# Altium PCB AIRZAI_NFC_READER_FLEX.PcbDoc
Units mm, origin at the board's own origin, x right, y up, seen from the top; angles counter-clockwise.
Board outline 158.45 x 20.7 mm, 2 copper layers (Top Layer, Bottom Layer); 39 components, 43 nets, 189 pads, 9 vias.
Unrouted connection lines stored in the file: 129.
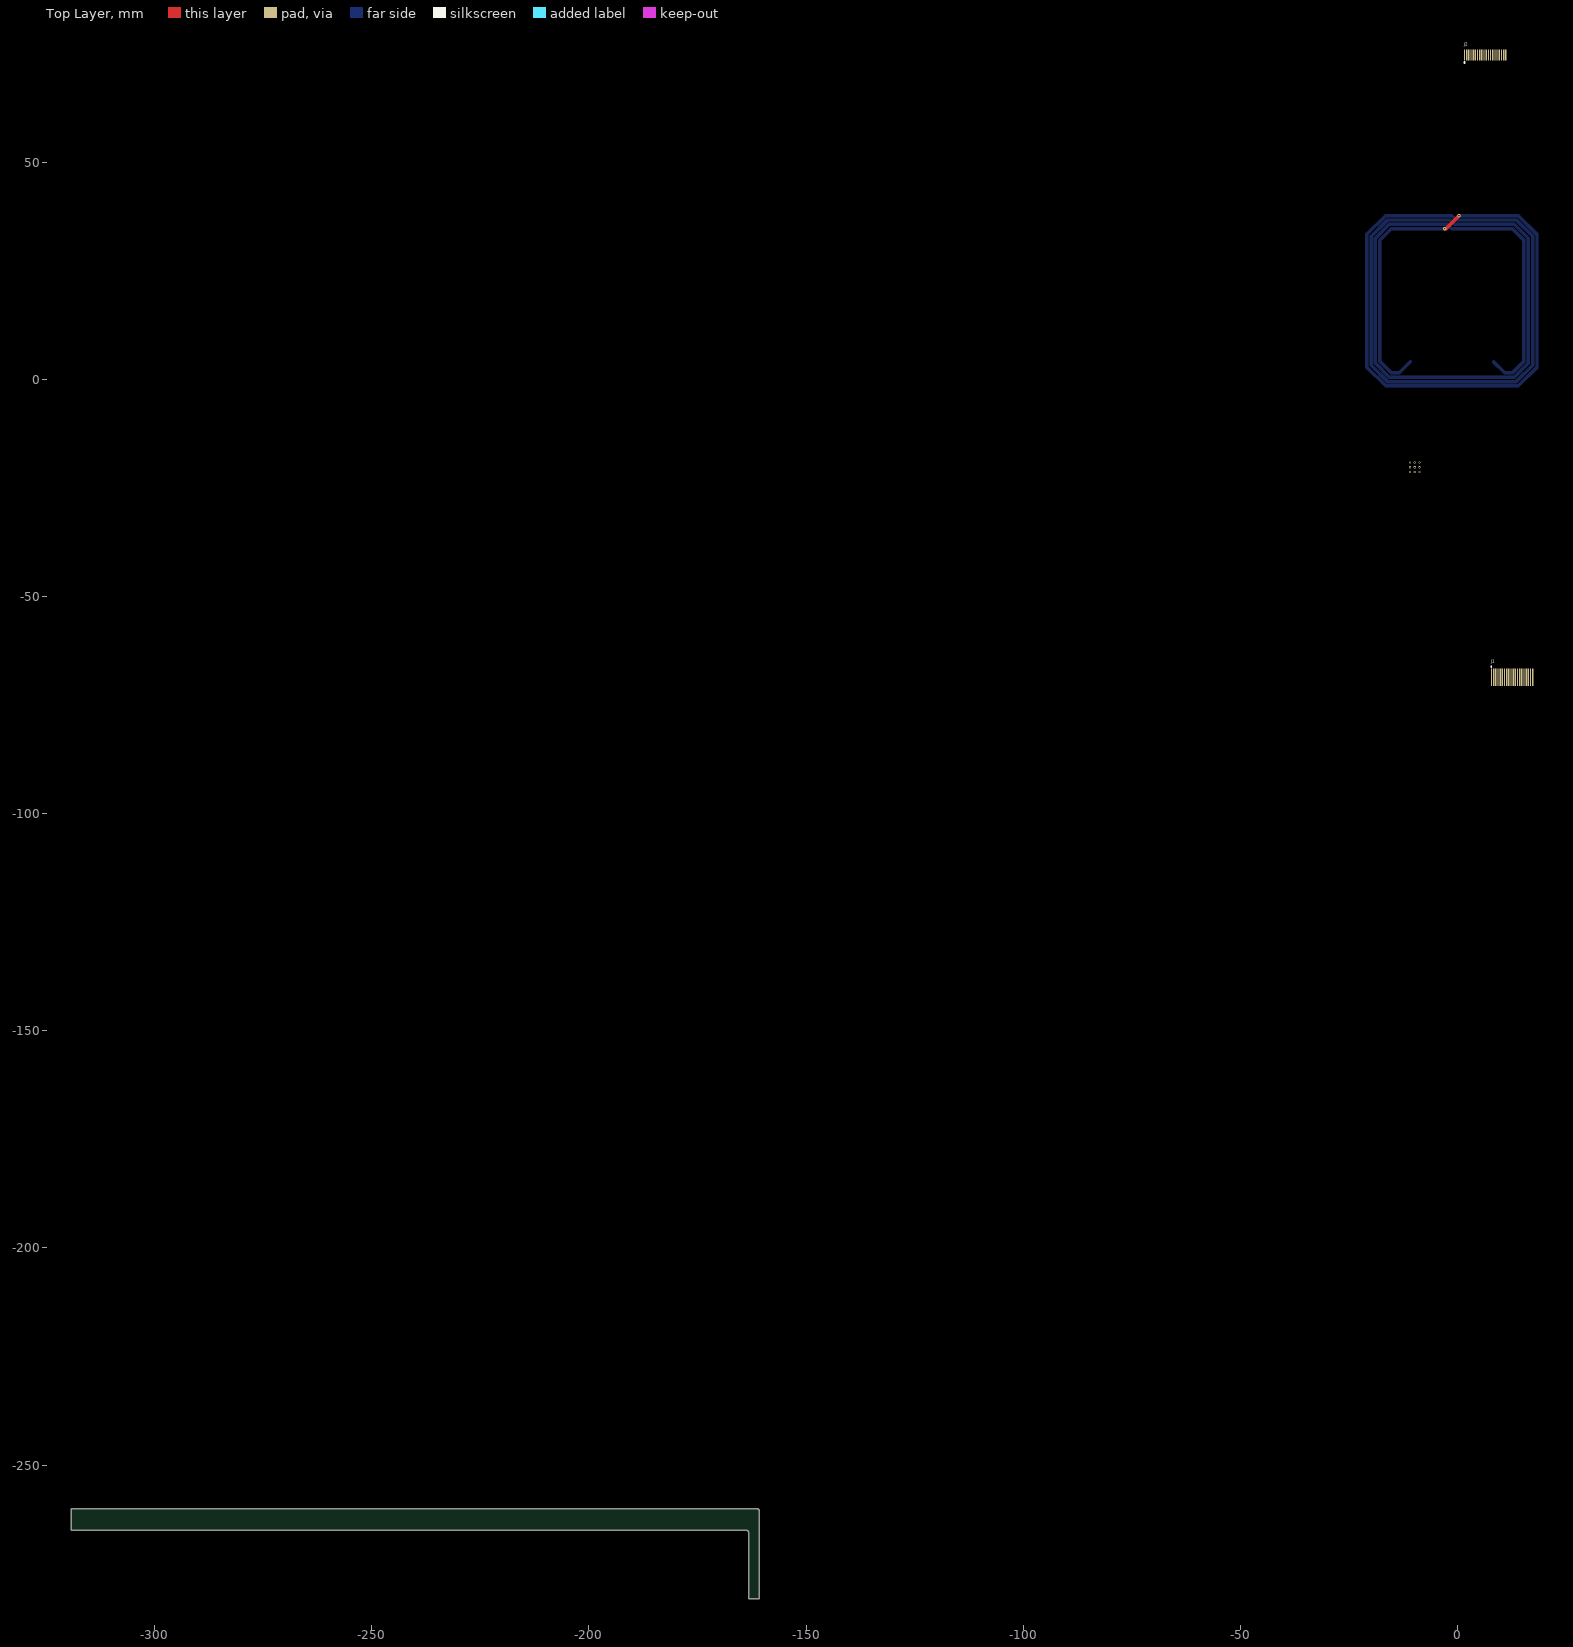
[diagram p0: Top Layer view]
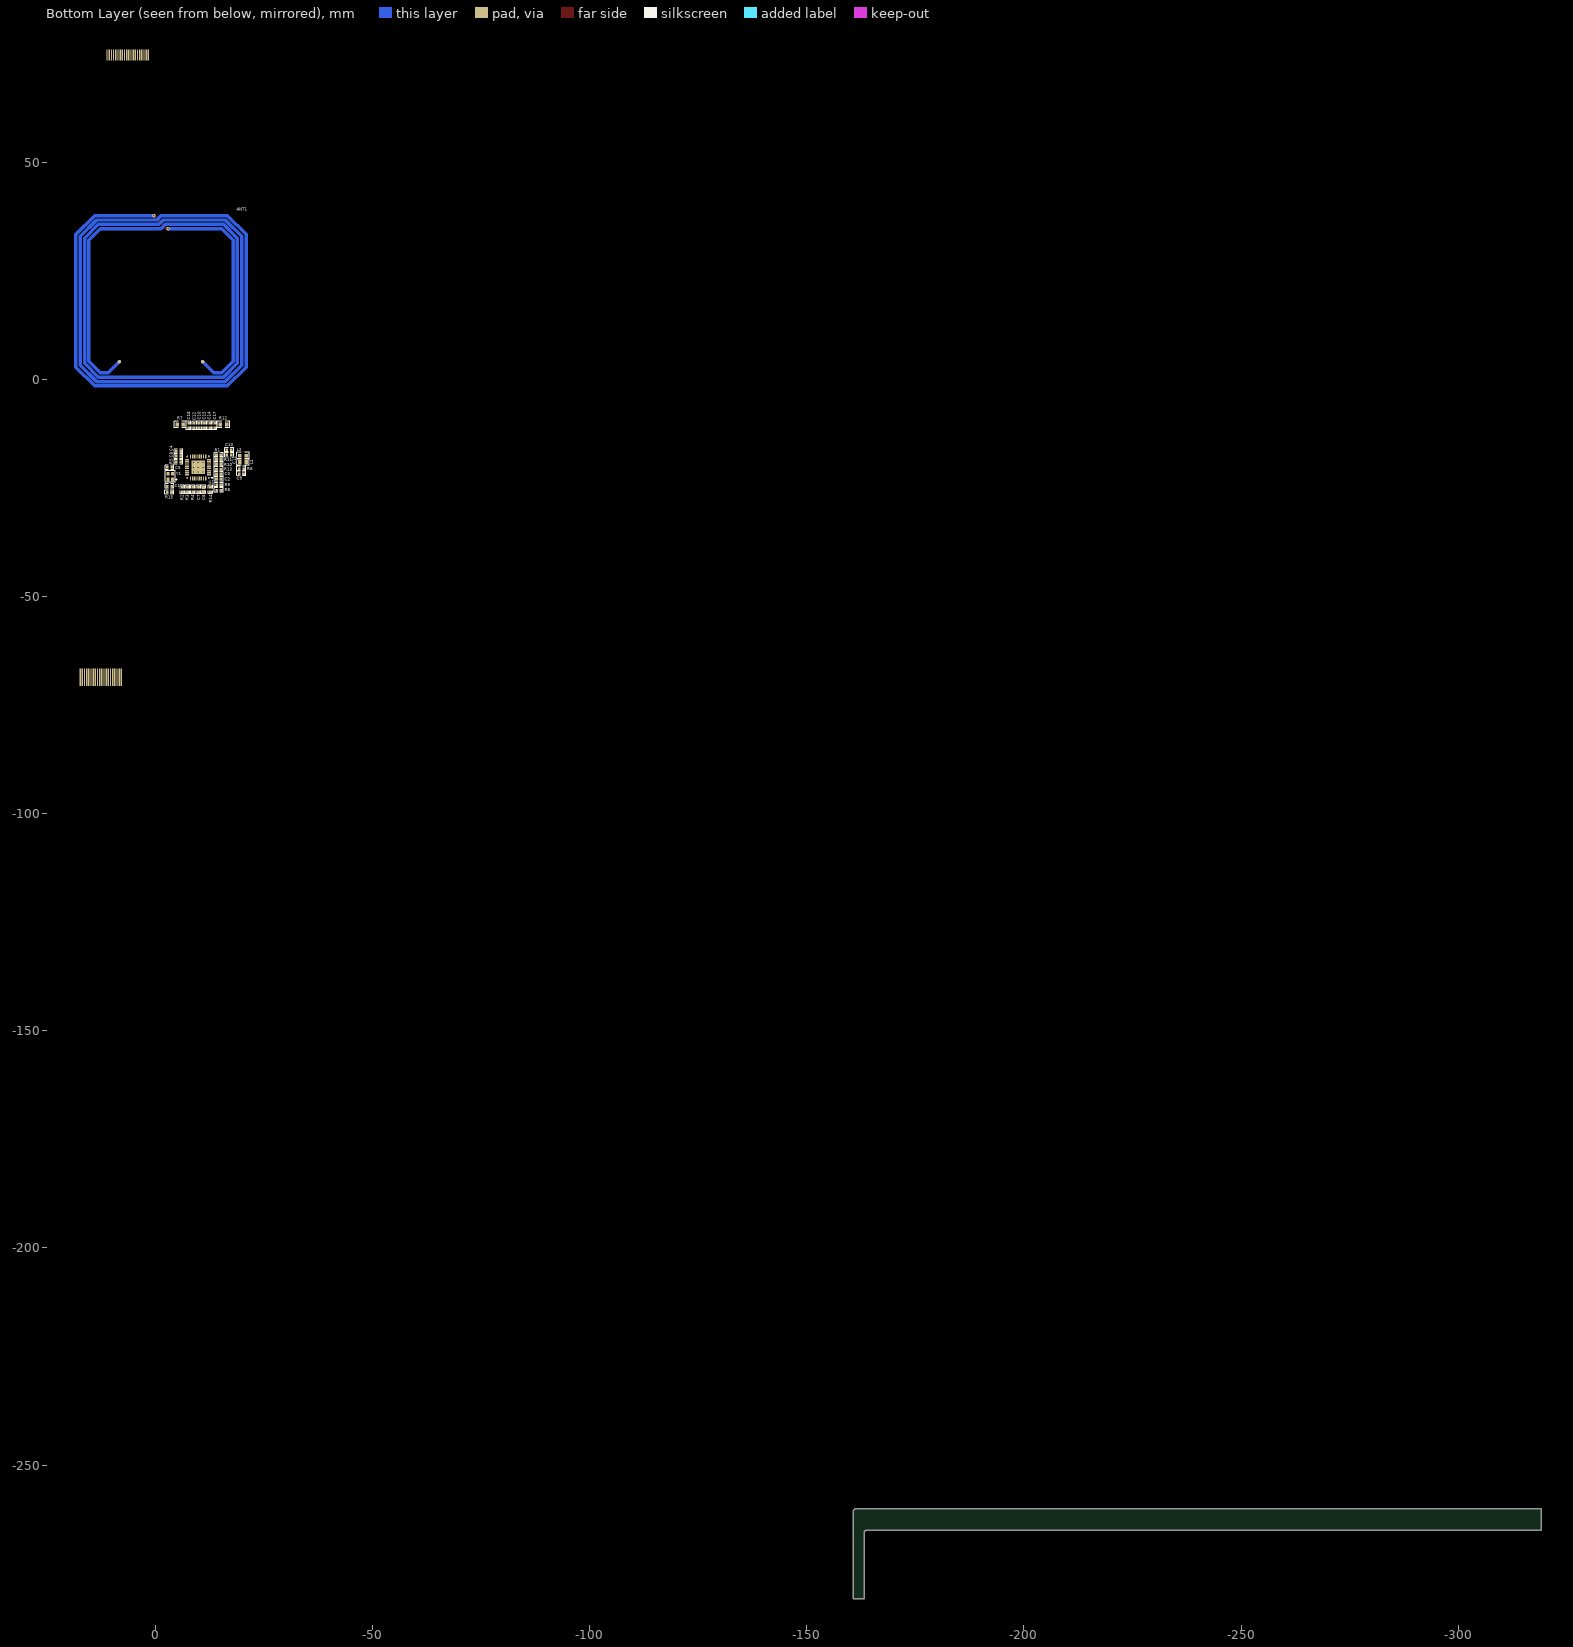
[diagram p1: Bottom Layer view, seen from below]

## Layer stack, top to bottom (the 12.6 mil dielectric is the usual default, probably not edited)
Top Solder: solder mask 0.0102, Solder Resist, Dk 3.5
Top Layer: signal copper 0.0356
Dielectric 1: dielectric 0.32, FR-4, Dk 4.8
Bottom Layer: signal copper 0.0356
Bottom Solder: solder mask 0.0102, Solder Resist, Dk 3.5

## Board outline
-319.17,-265.057 -319.17,-260.057 -161.356,-260.057 cw(c-161.356,-260.693) -160.72,-260.693 -160.72,-280.757 -163.22,-280.757 -163.22,-265.557 ccw(c-163.72,-265.557) -163.72,-265.057
board region "Layer Stack Region 1": -160.72,-274.15 -160.72,-280.757 -163.22,-280.757 -163.22,-274.15
board region "Layer Stack Region 1": -163.22,-273.337 -163.22,-265.557 -163.229,-265.459 -163.304,-265.279 -163.442,-265.141 -163.622,-265.066 -163.72,-265.057 -319.17,-265.057 -319.17,-260.057 -161.356,-260.057 -161.229,-260.057 -160.995,-260.153 -160.816,-260.332 -160.72,-260.566 -160.72,-260.693 -160.72,-273.337
board region "Layer Stack Region 2": -163.22,-274.15 -163.22,-273.337 -160.72,-273.337 -160.72,-274.15

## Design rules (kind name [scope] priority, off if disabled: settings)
Clearance Clearance_polygon_5V [OnLayer('Keep-Out Layer') vs (InNet('+5V') AND InPolygon)] p1: gap=0.254 ignorepadtopadclearanceinfootprint=FALSE
Clearance Clearance_POLYGON_KEEPOUT [(OnLayer('Keep-Out Layer')) vs (InNet('GND') AND InPolygon)] p2: gap=0.254 ignorepadtopadclearanceinfootprint=FALSE
Clearance [All] p3: gap=0.152 ignorepadtopadclearanceinfootprint=FALSE
MinimumSolderMaskSliver [All] p1: minsoldermaskwidth=0.025
PolygonConnect [All] p1: connectstyle=Direct reliefconductorwidth=0.254 reliefentries=4 polygonreliefangle="90 Angle" airgapwidth=0.254
RoomDefinition AIRZAI_NFC_READER_FLEX [InComponentClass('AIRZAI_NFC_READER_FLEX')] p1: confinementstyle=ConfineIn formatcopy=TRUE lockcomponents=FALSE outline -425.447,-395.268 -53.083,-395.268 -53.083,-151.428 -425.447,-151.428
RoutingVias [All] p1: holewidth=0.711 width=1.27 viastyle="Through Hole" minholewidth=0.203 minwidth=0.406 maxholewidth=0.711 maxwidth=1.27
SilkToSilkClearance [All] p1: silktosilkclearance=0.025
SilkToSolderMaskClearance [IsPad] p1: minsilkscreentomaskgap=0.051 clearancetoexposedcopper=TRUE
SolderMaskExpansion [All] p1: expansion=0.102
UnRoutedNet [All] p1: checkbadconnections=TRUE
Width [All] p1: maxlimit=2.54 minlimit=0.152 preferedwidth=0.254
26 further rules are at their usual default settings.

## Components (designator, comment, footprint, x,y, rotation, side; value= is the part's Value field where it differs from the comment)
ANT1 "NFC_ANT" ANTENNA-NFC-40MMX40MM -1.257,18.123 r0 bottom
C1 "12pF" 0402CAP -3.2,-24.562 r180 bottom
C2 "0.1µF" 0402CAP -14.554,-22.908 r180 bottom
C3 "0.1µF" 0402CAP -14.554,-21.773 r180 bottom
C4 "0.1µF" 0402CAP -5.283,-16.527 r0 bottom
C5 "12pF" 0402CAP -3.2,-20.244 r0 bottom
C6 "1uF" CAPC0402(1005)60_M -11.086,-25.349 r90 bottom
C7 "0.1µF" 0402CAP -9.892,-25.349 r270 bottom
C8 "0.1µF" 0402CAP -5.283,-17.696 r0 bottom
C9 "1nF" 0402CAP -19.771,-21.692 r0 bottom
C10 "18pF" 0402CAP -10.116,-10.603 r270 bottom
C11 "220pF" 0402CAP -16.95,-17.379 r180 bottom
C12 "47pF" 0402CAP -8.947,-10.603 r90 bottom
C13 "220pF" 0402CAP -16.95,-16.185 r0 bottom
C14 "47pF" 0402CAP -12.452,-10.603 r270 bottom
C15 "18pF" 0402CAP -11.284,-10.603 r270 bottom
C16 "DNP" 0402CAP -7.637,-10.603 r90 bottom
C17 "DNP" 0402CAP -13.621,-10.611 r270 bottom
J1 "FFC Cable" FFC_Pads_MBD 10.612,-68.58 r180 top
J2 "FFC Cable" FFC_PADS_LID 4.403,74.701 r180 top
L1 "560nH" 0603CAP -20.152,-19.05 r0 bottom
L2 "560mH" 0603CAP -20.152,-17.577 r0 bottom
R1 "0R" 0402 -14.549,-17.348 r180 bottom
R2 "10K" 0402 -6.164,-25.324 r90 bottom
R3 "10K" 0402 -7.358,-25.324 r90 bottom
R4 "10K" 0402 -8.571,-25.324 r90 bottom
R5 "1K" 0402 -5.29,-18.974 r180 bottom
R6 "2.7K" 0402 -19.779,-20.523 r180 bottom
R7 "3.3" 0603 -5.671,-10.349 r180 bottom
R8 "10K" 0402 -14.58,-25.476 r180 bottom
R9 "10K" 0402 -14.58,-24.257 r180 bottom
R10 "0R" 0402 -14.554,-19.533 r180 bottom
R11 "0R" 0402 -14.549,-18.44 r180 bottom
R12 "3.3" 0603 -15.653,-10.349 r0 bottom
R13 "10K" 0402 -14.549,-20.65 r180 bottom
R14 "0R" 0402 -12.66,-25.349 r270 bottom
R15 "0R" 0402 -3.183,-25.984 r0 bottom
U1 "MFRC52202HN1,115" VFQFN-32-MFRC52202HN1,157 -9.804,-20.236 r0 bottom
Y1 "27.12MHz" XTAL_2016 -3.378,-22.377 r90 bottom

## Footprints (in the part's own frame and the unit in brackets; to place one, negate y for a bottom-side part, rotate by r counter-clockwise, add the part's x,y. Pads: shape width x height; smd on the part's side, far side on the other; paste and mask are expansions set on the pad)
0402 [mm] "Chip Resistor, Body 1.1x0.5mm, IPC High Density"
  rect 0.6x0.6 smd: 1(-0.5,0) 2(0.5,0)
  silkscreen extent -1.02,-0.51 1.02,0.51, body extent -0.5,-0.25 0.5,0.25, height 0.27
0402CAP [mm] "Chip Capacitor, Body 1.1x0.5mm, IPC High Density"
  rect 0.6x0.6 smd: 1(-0.5,0) 2(0.5,0)
  silkscreen extent -1.02,-0.51 1.02,0.51, body extent -0.5,-0.3 0.5,0.3, height 0.19
0603 [mm] "Chip Resistor, Body 1.6x0.8mm, IPC High Density"
  rect 0.8x0.9 smd: 1(-0.7,0) 2(0.7,0)
  silkscreen extent -1.4,-0.76 1.4,0.76, body extent -0.8,-0.41 0.8,0.4, height 0.37
0603CAP [mm] "Chip Capacitor, Body 1.6x0.8mm, IPC High Density"
  rect 0.8x0.9 smd: 1(-0.7,0) 2(0.7,0)
  silkscreen extent -1.4,-0.76 1.4,0.76, body extent -0.8,-0.4 0.8,0.4, height 0.29
ANTENNA-NFC-40MMX40MM [mil] "ANTENNA-ID2+10P-01"
  round 31.5 smd: 1(-377.5,552.5) 2(377.5,552.5)
  round 30 hole 15: 1(-65,-653.54) 2(65,-771.65)
  Top Layer lines w31.5: -377.5,552.5 -478.54,653.54 -550,653.54 -653.54,550 -653.54,-550 -550,-653.54 -65,-653.54 ; 65,-771.65 601.26,-771.65 771.65,-601.26 771.65,601.26 601.26,771.65 -601.26,771.65 -771.65,601.26 -771.65,-601.26 -601.26,-771.65 0,-771.65 39.37,-732.28 584.17,-732.28 732.28,-584.17 732.28,584.17 584.17,732.28 -584.17,732.28 -732.28,584.17 -732.28,-584.17 -584.17,-732.28 -19.37,-732.28 20,-692.91 567.09,-692.91 692.91,-567.09 692.91,567.09 567.09,692.91 -567.09,692.91 -692.91,567.09 -692.91,-567.09 -567.09,-692.91 -39.37,-692.91 0,-653.54 550,-653.54 653.54,-550 653.54,550 550,653.54 478.54,653.54 377.5,552.5
  Bottom Layer lines w31.5: -65,-653.54 -53.11,-653.54 65,-771.65
CAPC0402(1005)60_M [mm] "Chip Capacitor, Body 1.0x0.5mm, Height 0.6mm, IPC Low Density"
  rect 0.72x0.72 smd: 1(-0.5,0) 2(0.5,0)
  silkscreen extent -1.02,-0.51 1.02,0.51, body extent -0.55,-0.3 0.55,0.3, height 0.6
FFC_PADS_LID [mm] "(0.50mm"
  rect 0.3x2.6 smd: 1(2.75,0) 2(2.25,0) 3(1.75,0) 4(1.25,0) 5(0.75,0) 6(0.25,0) 7(-0.25,0) 8(-0.75,0) 9(-1.25,0) 10(-1.75,0) 11(-2.25,0) 12(-2.75,0) 13(-3.25,0) 14(-3.75,0) 15(-4.25,0) 16(-4.75,0) 17(-5.25,0) 18(-5.75,0) 19(-6.25,0) 20(-6.75,0)
  rect 0.3x2.6 smd far side: 1(2.75,0) 2(2.25,0) 3(1.75,0) 4(1.25,0) 5(0.75,0) 6(0.25,0) 7(-0.25,0) 8(-0.75,0) 9(-1.25,0) 10(-1.75,0) 11(-2.25,0) 12(-2.75,0) 13(-3.25,0) 14(-3.75,0) 15(-4.25,0) 16(-4.75,0) 17(-5.25,0) 18(-5.75,0) 19(-6.25,0) 20(-6.75,0)
  silkscreen extent 2.62,1.58 2.87,1.83
FFC_Pads_MBD [mm] "(0.50mm"
  rect 0.3x4 smd: 1(2.75,0) 2(2.25,0) 3(1.75,0) 4(1.25,0) 5(0.75,0) 6(0.25,0) 7(-0.25,0) 8(-0.75,0) 9(-1.25,0) 10(-1.75,0) 11(-2.25,0) 12(-2.75,0) 13(-3.25,0) 14(-3.75,0) 15(-4.25,0) 16(-4.75,0) 17(-5.25,0) 18(-5.75,0) 19(-6.25,0) 20(-6.75,0)
  rect 0.3x4 smd far side: 1(2.75,0) 2(2.25,0) 3(1.75,0) 4(1.25,0) 5(0.75,0) 6(0.25,0) 7(-0.25,0) 8(-0.75,0) 9(-1.25,0) 10(-1.75,0) 11(-2.25,0) 12(-2.75,0) 13(-3.25,0) 14(-3.75,0) 15(-4.25,0) 16(-4.75,0) 17(-5.25,0) 18(-5.75,0) 19(-6.25,0) 20(-6.75,0)
  silkscreen extent 2.64,-2.56 2.89,-2.31
VFQFN-32-MFRC52202HN1,157 [mm]
  rect 0.9x0.31 smd: 1(-2.529,1.75) 2(-2.529,1.25) 3(-2.529,0.75) 4(-2.529,0.25) 5(-2.529,-0.25) 6(-2.529,-0.75) 7(-2.529,-1.25) 8(-2.529,-1.75) 17(2.529,-1.75) 18(2.529,-1.25) 19(2.529,-0.75) 20(2.529,-0.25) 21(2.529,0.25) 22(2.529,0.75) 23(2.529,1.25) 24(2.529,1.75)
  rect 0.31x0.9 smd: 9(-1.75,-2.529) 10(-1.25,-2.529) 11(-0.75,-2.529) 12(-0.25,-2.529) 13(0.25,-2.529) 14(0.75,-2.529) 15(1.25,-2.529) 16(1.75,-2.529) 25(1.75,2.529) 26(1.25,2.529) 27(0.75,2.529) 28(0.25,2.529) 29(-0.25,2.529) 30(-0.75,2.529) 31(-1.25,2.529) 32(-1.75,2.529)
  rect 3.1x3.1 smd: 33(0,0)
  silkscreen extent -3.32,-2.55 2.55,2.55, body extent -2.55,-2.55 2.55,2.55, height 1
XTAL_2016 [mm] "2.00mm x 1.60mm"
  rect 0.85x0.75 smd: 1(-0.675,-0.525) 2(0.675,-0.525) 3(0.675,0.525) 4(-0.675,0.525)
  silkscreen extent -1.32,-1.47 1.32,1.14, body extent -1,-0.81 1,0.79, height 0.65

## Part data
C1 C5: library part CAP, "CAP CER 12PF 50V C0G/NP0 0402", Case/Package=0402, Case Code (Metric)=1005, Dielectric=C0G, Dielectric Material=Ceramic, Manufacturer=KEMET, Manufacturer Part Number=C0402C120J5GACTU, Max Operating Temperature=125°C, Min Operating Temperature=-55°C, Package Quantity=1, Supplier Part Number 1=399-1013-6-ND, Temperature Coefficient=30ppm/°C, Tolerance=5%, Voltage=50V
C2 C3 C4 C7 C8: library part C0402-100n, "Capacitor, X7R, ±10%", Case-EIA=0402, Case-Metric=1005, Manufacturer=TDK, Manufacturer Part Number=C1005X7R1C104K, Rated Voltage="16 V", Supplier Part Number 1=445-4952-2-ND, Tolerance=±20%
C6: library part CAP, "CAP 1uF 16V ±10% 0402 (1005 Metric) Thickness 0.6mm SMD", Case/Package=0402, Case Code (Metric)=1005, Dielectric=X5R, Manufacturer="Taiyo Yuden", Manufacturer Part Number=EMK105BJ105KV-F, Max Operating Temperature=85°C, Min Operating Temperature=-55°C, Package Quantity=1, Supplier Part Number 1=587-2477-6-ND, Tolerance=10%, Voltage Rating=16V
C9: library part 56p, "CAP CER 1000PF 50V C0G/NP0 0402", Case/Package=0402, Case Code (Metric)=1005, Dielectric=C0G, Manufacturer=Murata, Manufacturer Part Number=GRM1555C1H102FA01D, Max Operating Temperature=125°C, Min Operating Temperature=-55°C, Package Quantity=1, Supplier Part Number 1=490-6189-1-ND, Tolerance=1%, Voltage=50V
C10 C15: library part 56p, "CAP CER 18PF 50V NP0 0402", Case/Package=0402, Case Code (Metric)=1005, Dielectric=C0G, Manufacturer="Kyocera AVX", Manufacturer Part Number=04025U180FAT2A, Max Operating Temperature=125°C, Min Operating Temperature=-55°C, Package Quantity=10000, Supplier Part Number 1=478-10144-1-ND, Tolerance=1%, Voltage Rating=50V
C11 C13: library part 56p, "CAP CER 220PF 50V NPO 0402", Case/Package=0402, Case Code (Metric)=1005, Dielectric=C0G, Manufacturer=Yageo, Manufacturer Part Number=CC0402FRNPO9BN221, Max Operating Temperature=125°C, Min Operating Temperature=-55°C, Supplier Part Number 1=311-3730-1-ND, Tolerance=1%, Voltage Rating=50V
C12 C14: library part 56p, "CAP CER 47PF 50V C0G/NP0 0402", Dielectric=C0G, Manufacturer=Murata, Manufacturer Part Number=GJM1555C1H470FB01D, Supplier Part Number 1=490-16376-1-ND, Tolerance=1%, Voltage Rating (DC)=50V
C16 C17: library part 56p
J1 J2: library part XF2M-2015-1A-R100, "Cable"
L1: library part Inductor, "FIXED IND 560NH 100MA 1.05 OHM", Case/Package=0603, Case Code (Metric)=1608, Current Rating=100mA, DC Resistance (DCR)=1.05R, Manufacturer=TDK, Manufacturer Part Number=MLF1608DR56JTD25, Max DC Current=30mA, Max Operating Temperature=125°C, Min Operating Temperature=-55°C, Package Quantity=4000, Ratings=AEC-Q200, Self Resonant Frequency=170MHz, Supplier Part Number 1=445-16970-1-ND, Test Frequency=25MHz, Tolerance=5%
L2: library part Inductor, "FIXED IND 560NH 100MA 1.05 OHM", Case/Package=0603, Case Code (Metric)=1608, Current Rating=100mA, DC Resistance (DCR)=1.05R, Inductance=560nH, Manufacturer=TDK, Manufacturer Part Number=MLF1608DR56JTD25, Max DC Current=30mA, Max Operating Temperature=125°C, Min Operating Temperature=-55°C, Package Quantity=4000, Ratings=AEC-Q200, Self Resonant Frequency=170MHz, Supplier Part Number 1=445-16970-1-ND, Test Frequency=25MHz, Tolerance=5%
R1 R10 R11 R14 R15: library part R0402-12k, "Resistor, ±1%, 0.063W", Case-EIA=0402, Case-Metric=1005, Manufacturer=Panasonic, Manufacturer Part Number=ERJ-2GE0R00X, Supplier Part Number 1=P0.0JTR-ND, Tolerance=±5%
R2 R3 R4 R8 R9 R13: library part R0402-12k, "Resistor 10K, ±1%, 0.063W", Case/Package=0402, Case Code (Metric)=1005, Manufacturer="Vishay Dale", Manufacturer Part Number=CRCW040210K0JNED, Max Operating Temperature=155°C, Max Power Dissipation=63mW, Min Operating Temperature=-55°C, Package Quantity=1, Resistance=10kR, Supplier Part Number 1=541-10KJDKR-ND, Temperature Coefficient=200ppm/°C, Tolerance=5%, Voltage Rating=50V
R5: library part R0402-12k, "RES SMD 1K OHM 1% 1/16W 0402", Case/Package=0402, Case Code (Metric)=1005, Manufacturer=Yageo, Manufacturer Part Number=RC0402FR-071KL, Max Operating Temperature=155°C, Min Operating Temperature=-55°C, Power Rating=62.5mW, Resistance=1kR, Supplier Part Number 1=311-1.00KLRCT-ND, Temperature Coefficient=100ppm/°C, Tolerance=1%, Voltage Rating=50V
R6: library part R0402-12k, "RES SMD 2.7K OHM 1% 1/16W 0402", Case/Package=0402, Manufacturer="Yageo Phycomp", Manufacturer Part Number=RC0402FR-072K7L, Max Operating Temperature=155°C, Min Operating Temperature=-55°C, Power Rating=63mW, Resistance=2.7kR, Supplier Part Number 1=311-2.70KLRCT-ND, Temperature Coefficient=100ppm/°C, Tolerance=1%, Voltage Rating (DC)=50V
R7 R12: library part R0402-12k, "RES SMD 3.3 OHM 1% 1/10W 0603", Case/Package=0603, Manufacturer=Yageo, Manufacturer Part Number=AC0603FR-073R3L, Max Operating Temperature=155°C, Max Power Dissipation=100mW, Min Operating Temperature=-55°C, Resistance=3.3R, Supplier Part Number 1=YAG5335CT-ND, Temperature Coefficient=200ppm/°C, Tolerance=1%
U1: library part MFRC52201HN1,157, "IC RFID READER 13.56MHZ 32HVQFN", Frequency=13.56MHz, Manufacturer="NXP Semiconductors", Max Operating Temperature=85°C, Min Operating Temperature=-25°C, Package Quantity=1500, Supplier Part Number 1=568-15200-1-ND
Y1: library part ZTB_2, "CRYSTAL 27.12MHZ 10PF SMD", Manufacturer="ECS International", Manufacturer Part Number=ECS-271.2-10-37-CKM-TR, Supplier Part Number 1=XC2511DKR-ND

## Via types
v1: diameter 0.5, hole 0.203, Top Layer to Bottom Layer, 9 vias

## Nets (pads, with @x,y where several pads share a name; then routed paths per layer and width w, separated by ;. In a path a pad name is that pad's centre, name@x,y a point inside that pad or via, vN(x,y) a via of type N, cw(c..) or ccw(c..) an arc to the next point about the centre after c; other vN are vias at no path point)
3V3: C2.1 C3.1 C4.1 C6.2 C7.1 J1.18 J2.18 R1.2 R9.2 R13.2 U1.2 U1.3 U1.12 U1.15
+5: J1.19 J1.20 J2.19 J2.20
ACCELERO_INT: J1.14 J2.14
ADC_CH1: J1.5 J2.5
CAP1_TOUCH_OUT: J1.7 J2.7
CAP2_TOUCH_OUT: J1.8 J2.8
EN: J1.17 J2.17
GND: C1.1 C2.2 C3.2 C4.2 C5.1 C6.1 C7.2 C8.2 C11.1 C12.1 C13.2 C14.2 C16.1 C17.2 J1.1 J1.2 J2.1 J2.2 R2.1 R3.1 R4.1 R8.2 R10.2 R11.2 U1.4 U1.5 U1.10 U1.14 U1.18 U1.33 Y1.2 Y1.4
  other v1: -10.904,-21.336 -9.804,-21.336 -8.704,-21.336 -10.904,-20.236 -9.804,-20.236 -8.704,-20.236 -10.904,-19.136 -9.804,-19.136 -8.704,-19.136
"LED Str CLK": J1.10 J2.10
"LED Str DATA": J1.11 J2.11
NetANT1_1: ANT1.1 R7.1
NetANT1_2: ANT1.2 R12.1
NetC1_2: C1.2 U1.21 Y1.3
NetC5_2: C5.2 U1.22 Y1.1
NetC9_1: C9.1 R6.2
NetC9_2: C9.2 R5.2 U1.17
NetC10_1: C10.1 C12.2 C16.2 R7.2
NetC10_2: C10.2 C11.2 L1.2 R6.1
NetC13_1: C13.1 C15.2 L2.2
NetC14_1: C14.1 C15.1 C17.1 R12.2
NetL1_1: L1.1 U1.11
NetL2_1: L2.1 U1.13
NetR1_1: R1.1 U1.9
NetR2_2: R2.2 U1.28
NetR3_2: R3.2 U1.29
NetR4_2: R4.2 U1.30
NetR8_1: R8.1 U1.32
NetR9_1: R9.1 U1.1
NetR10_1: R10.1 U1.7
NetR11_1: R11.1 U1.8
NetR13_1: R13.1 U1.6
NetR14_1: R14.1 U1.31
NetR15_1: R15.1 U1.24
NetTP2_1: U1.23
NFC_INT: J1.12 J2.12
PWM1: J1.4 J2.4
PWM2: J1.3 J2.3
SCL: J1.15 J2.15 R14.2
SDA: J1.16 J2.16 R15.2
SPR_GPO1: J1.9 J2.9
SPR_GPO2: J1.6 J2.6
TOFINT: J1.13 J2.13
VMID: C8.1 R5.1 U1.16
pads on no net: U1.19 U1.20 U1.25 U1.26 U1.27

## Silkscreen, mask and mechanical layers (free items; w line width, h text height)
Mechanical 1:
  drawing of 4182 lines, arcs and shapes, not listed
  text "6" at -202.432,156.213 h3.08
  text "5" at -112.432,156.213 h3.08
  text "4" at -22.432,156.213 h3.08
  text "3" at 67.568,156.213 h3.08
  text "2" at 157.568,156.213 h3.08
  text "1" at 247.568,156.213 h3.08
  text "APPD/DATE" at 285.74,147.702 h2.05
  text "ZONE" at 147.101,147.636 h2.05
  text "ECN" at 124.542,147.559 h2.05
  text "ISSUE" at 135.822,147.559 h2.05
  text "DESCRIPTION" at 198.767,147.559 h2.05
  text "DRN/DATE" at 254.828,147.559 h2.05
  text "CHK/DATE" at 270.395,147.559 h2.05
  text "NOTE: THIS DRAWING WAS PRODUCED BY COMPUTER, DO NOT UPDATE MANUALLY" at -242.391,143.775 h4
  text "E" at -250.852,113.607 h3.08
  text "E" at 297.931,113.607 h3.08
  text "9,35" at 130.353,74.586 h3.5
  text "R0,4" at -116.039,66.513 h3.5 r322.13
  text "R0,4" at -110.21,65.867 h3.5 r28.27
  text "R0,4" at -121.896,61.804 h3.5 r49.62
  text "1,9" at 163.004,57.099 h3.5 r90
  text "18,3" at 178.473,53.044 h3.5 r90
  text "R0,4" at -103.845,47.467 h3.5 r346.55
  text "R1,5" at -106.017,39.931 h3.5 r297.71
  text "5,7" at 131.444,39.183 h3.5
  text "D" at -250.852,37.607 h3.08
  text "D" at 297.931,37.607 h3.08
  text "10,6" at 21.267,33.599 h3.5
  text "42,2" at 178.451,22.795 h3.5 r90
  text "3,2" at 140.948,11.222 h3.5
  text "R1,5" at -112.196,10.296 h3.5 r52.37
  text "R1,7" at -109.771,5.551 h3.5 r19.46
  text "56" at 178.254,-26.305 h3.5 r90
  text "C" at -251.145,-38.393 h3.08
  text "C" at 297.931,-38.393 h3.08
  text "~}" at -9.206,-39.713 h3.5
  text "R1,7" at -106.648,-50.41 h3.5 r337.84
  text "R1,7" at -112.22,-50.59 h3.5 r324.73
  text "3,2" at 134.907,-53.737 h3.5
  text "R0,4" at -110.186,-57.309 h3.5 r323.84
  text "2" at 137.085,-68.3 h3.5
  text "6" at 178.201,-68.437 h3.5 r90
  text "B" at -250.852,-114.393 h3.08
  text "B" at 297.931,-114.393 h3.08
  text "Coremi Industries Co., Limited" at 179.197,-186.004 h5
  text "T10" at 279.02,-189.771 h3.5
  text "A" at -251.731,-190.393 h3.08
  text "A" at 297.931,-190.393 h3.08
  text "REVISION NO." at 254.01,-190.756 h2.53
  text "DRAWING NO." at 179.146,-192.456 h2.53
  text "Airzai-041T10" at 210.744,-193.04 h3.5
  text "Airzai" at 258.447,-194.618 h3.5
  text "MODEL :" at 242.01,-196.756 h2.53
  text "MANIFOLD_SOLID_BREP_27740" at 193.116,-197.866 h2.5
  text "TITLE:" at 178.791,-197.917 h2.53
  text "METERIAL:" at 179.01,-202.756 h2.53
  text "MASS :                 kg" at 242.01,-202.756 h2.53
  text "1" at 223.565,-207.8 h3.5
  text "P/N:" at 242.01,-208.519 h3
  text "FINISH:" at 179.01,-208.756 h2.53
  text "QTY:" at 211.51,-208.756 h2.53
  text "NOTE:" at -228.611,-210.877 h3
  text ".  TOLERANCES  ." at 210.727,-212.933 h2.02
  text "1:1" at 192.524,-213.584 h3.5
  text "1.UNSPECIFIED DRAFT ANGLE 1.0\Fgdt;{\Fgdt;~}" at -228.611,-213.907 h3
  text "SCALE:" at 179.01,-214.756 h2.53
  text "DRN.DATE" at 242.01,-214.756 h2.53
  text "Daniel Apr/20,2019" at 258.608,-215.364 h3
  text "All dimensions are in mm" at 210.565,-216.262 h1.52
  text "\Ftxt;2.UNSPECIFIED FILLET TO BE R0.3" at -228.611,-216.937 h3
  text "Daniel Apr/20,201" at 258.608,-218.394 h3
  text "unless otherwise specified." at 210.808,-219.014 h1.52
  text "A2" at -244.579,-220.635 h6
  text "PROJECTION" at 179.01,-220.756 h2.53
  text "CHK.DATE" at 242.01,-220.756 h2.53
  text "X" at 218.231,-221.462 h1.52
  text "0.20" at 228.572,-221.462 h1.52
  text ".X" at 218.231,-223.667 h1.52
  text "0.10" at 228.572,-223.667 h1.52
  text ".XX" at 218.231,-225.872 h1.52
  text "0.05" at 228.572,-225.872 h1.52
  text "1  1" at 192.164,-226.489 h3.5
  text "SHEET   OF" at 179.01,-226.756 h2.53
  text "APP.DATE" at 242.01,-226.756 h2.53
  text "ANGLE" at 217.842,-228.077 h1.52
  text "~}" at 228.572,-228.077 h1.52
  text "6" at -202.432,-233.763 h3.08
  text "5" at -112.432,-233.763 h3.08
  text "4" at -22.432,-233.763 h3.08
  text "3" at 67.568,-233.763 h3.08
  text "2" at 157.568,-233.763 h3.08
  text "1" at 247.568,-233.763 h3.08
Mechanical 2:
  lines w0.013: 199.06,-221.415 203.701,-221.415 ; 201.38,-223.735 201.38,-219.094 ; 202.664,-221.431 209.974,-221.431
Mechanical 4:
  lines w0.013: 1.115,76.77 1.115,-3.306 7.315,-54.306 7.315,-70.753 17.915,-70.753 17.915,-54.306 11.715,-3.306 11.715,76.77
